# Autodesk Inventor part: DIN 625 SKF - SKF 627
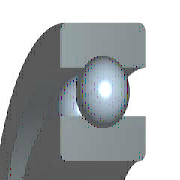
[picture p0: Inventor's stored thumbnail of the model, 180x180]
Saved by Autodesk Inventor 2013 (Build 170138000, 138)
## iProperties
IsCustomPart: 0
Created: 2012-02
Part Number: DIN 625 SKF - SKF 627
Material: Stahl, weich
Description: Kugellager, einreihig
Document SubType Name: Modeling
Standard: DIN 625
Designer: rYan
Standards Organization: DIN
Language: de-DE
Size Designation: SKF 627
Categories: <MemberInstance><Categories><Category DisplayName="Wellenteile" InternalName="7f7aeb1f-a693-4053-b835-cee3144e0d98" Mnemonic="SHFT"><Category DisplayName="Lager
Density: 7.86 g/cm^3
Mass: 12.2564 g
Surface Area: 20.5713 cm^2
Volume: 1.55934 cm^3
Author: rYan
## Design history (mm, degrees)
node "WorkPoint1"
revolve "Drehung1" stored, may be unused: angle "d6" = 360 deg
node "WorkAxis1"
node "WorkPlane3"
revolve "Drehung2" stored, may be unused: angle "d10" = 360 deg
node "WorkPlane4"
node "WorkPoint2"
sketch "Skizze5"
  geometry: L1 (7.25, 1.25)-(7.25, 5.75); L2 (8.6, 0)-(-8.6, 0) reference; L3 (7.25, 1.25)-(7.25, 5.75); A1 r 2.25 centre (7.25, 3.5) between (7.25, 1.25) and (7.25, 5.75); A2 r 2.25 centre (7.25, 3.5) between (8.6, 1.7) and (8.6, 5.3) reference
  constraints: 4 end point, 2 point on circle, 1 centre point, 1 concentric, 1 vertical
  dimensions: "d13" = 0 horizontal distance of A1.centre L1.start; "d15" = 4.5001 diameter of A1 (computed from msp_mdtd6)
revolve "Drehung3" sketch "Skizze5" stored, may be unused: angle "d16" = 360 deg
pattern_circular "Polare Anordnung1" dims "d17" = 52.33333 (= msp_pocet), angle "d19" = 360 deg
body "Solid1"
node "Skizze1"
node "Skizze4"
fillet "Rundung1" dims "d20" = 0.3 (= r)
sketch "Skizze2"
  geometry: L1 (3.5, 7)-(11, 7); L2 (3.5, 0)-(3.5, 7); L3 (11, 0)-(3.5, 0); L4 (11, 7)-(11, 0); L5 (0, 0)-(0, 20); L6 (0, 0)-(0, 20); L7 (-7.2, 0)-(43.2, 0) reference
  constraints: 12 end point, 3 vertical, 2 horizontal, 1 collinear, 1 other
  dimensions: "d1" = 7 vertical distance of L1.start L5 (= Diam); "d3" = 22 diameter of L1.end L5 (= DD); "d5" = 7 distance of L2.start L1.start (= msp_mdtd2)
sketch "Skizze3"
  geometry: L1 (8.6, 7)-(8.6, 5.3); L2 (5.9, 7)-(8.6, 7); L3 (5.9, 5.3)-(5.9, 7); L4 (5.9, 0)-(5.9, 1.7); L5 (8.6, 0)-(5.9, 0); L6 (8.6, 1.7)-(8.6, 0); L7 (11, 0)-(-11, 0) reference; L8 (11, 7)-(-11, 7) reference; L9 (0, -42.29)-(0, 61.29); L10 (0, 82.007)-(0, -63.007) reference; A1 r 2.25 centre (7.25, 3.5) between (8.6, 1.7) and (8.6, 5.3); A2 r 2.25 centre (7.25, 3.5) between (5.9, 5.3) and (5.9, 1.7)
  constraints: 14 end point, 4 collinear, 4 point on circle, 4 vertical, 2 centre point, 2 concentric, 2 horizontal, 2 point on line
  dimensions: "d9" = 4.5 diameter of A1 (= msp_mdtd6); "d21" = 5.9 distance between parallel lines of L9 L4 (= 0.5 x msp_d1); "d22" = 7.25 distance from line of L9 A1.centre (= 0.5 x msp_ds); "d23" = 8.6 distance between parallel lines of L9 L6 (= 0.5 x msp_dd1)
other parameters: "Diam" = 7 [user parameter; used in 3 equation terms], "DD" = 22 [user parameter; used in 3 equation terms], "B" = 7 [user parameter; used in 1 equation term], "r" = 0.3 [user parameter; used in 1 equation term], "msp_ds" = 14.5 (= 0.5 x Diam + 0.5 x DD) [user parameter; used in 5 equation terms], "msp_d0" = 4.5 (= -0.3 x Diam + 0.3 x DD) [user parameter; used in 4 equation terms], "msp_d1" = 11.8 (= msp_ds - 0.6 x msp_d0) [user parameter; used in 1 equation term], "msp_dd1" = 17.2 (= msp_ds + 0.6 x msp_d0) [user parameter; used in 1 equation term], "msp_pom" = 21.75 (= 1.5 x msp_ds) [user parameter; used in 1 equation term], "msp_mdtd2" = 7 (= B) [user parameter; used in 3 equation terms], "msp_mdtd4" = 14.5 (= msp_ds) [user parameter], "msp_mdtd6" = 4.5 (= msp_d0) [user parameter; used in 2 equation terms], "msp_mdtd7" = 3.5 (= 0.5 x msp_mdtd2) [user parameter], "msp_pocet" = 52.33333 (computed from msp_d0, msp_pom) [user parameter; used in 1 equation term], "d2" = 72 (derived), "d4" = 19 (derived), "d7" = 0, "d8" = 15.6 (derived), "d11" = -7 (computed from msp_mdtd2), "d12" = 0 (derived), "d14" = 15.6001 (derived), "d26" = 0, "d27" = 0, "d28" = 0, "d29" = 0, "d30" = 0
